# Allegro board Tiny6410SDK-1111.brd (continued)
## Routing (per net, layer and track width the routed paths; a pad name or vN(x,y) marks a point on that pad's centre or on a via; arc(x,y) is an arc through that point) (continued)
GND_AC97: length 43.5
  TOP w0.305: U7.40 89.13,32.02 ; 89.13,32.02 89.63,32.52 U7.34 ; 89.13,32.02 88.13,31.02 ; U7.26 90.13,28.52 U7.49 ; U7.18 87.63,30.52 U7.49 ; U7.49 88.13,31.02 ; 88.13,31.02 U7.42
  TOP w0.508: C49.1 v1(91.82,38.48) ; C48.1 v1(88.01,39.5) ; R30.2 89.53,20.7 v1(88.9,21.34) ; C38.1 v1(97.16,34.42) ; C57.1 v1(97.16,31.62) ; C51.1 C53.1 86.87,22.35 86.49,21.97 v1(86.49,21.46) ; C34.2 v1(92.46,21.59) ; C23.1 v1(97.16,35.81) ; C39.1 v1(97.16,27.43) ; C40.1 v1(97.16,30.23) ; C33.2 v1(93.85,21.72) ; C60.1 v1(97.16,33.02) ; R26.2 v1(77.57,23.22) ; C27.1 v1(92.58,17.02) ; v1(97.16,26.42) 96.77,26.04 C25.1 ; C26.1 v1(97.16,28.83) ; C52.1 v1(91.06,21.46)
  TOP w0.559: v1(77.72,22.1) 78.61,22.99 R26.2 ; C61.1 80.14,27.69 79.73,27.28 v1(79.73,27.01)
  vias: v1(79.38,19.68) v1(79.38,18.54) v1(83.57,21.46) v1(84.71,21.46) v1(85.98,28.96) v1(86.11,32.64) v1(86.11,30.99) v1(88.01,29.08) v1(88.14,32.64) v1(88.14,30.86) v1(89.53,30.86) v1(89.53,29.21)
GND_EARTH: length 4.2
  TOP w0.508: LAN.8 68.45,19.88 68.45,22.1 C145.1
VBUS: length 139.8
  TOP w0.203: C17.1 104.9,17.65
  TOP w0.508: MINIUSB.1 98.42,12.19 99.06,12.83 99.95,12.83 ; v1(31.02,101.01) 31.02,98.52 43.2,86.33 43.22,86.33 44.03,85.52 49.58,85.52 v1(49.78,85.72)
  TOP w0.762: v1(105.03,19.05) 104.9,18.92 104.9,17.65 104.65,17.4 C18.2 104.39,15.24 104.39,14.61 103.38,13.59 100.97,13.59 100.2,12.83 99.95,12.83
  BOTTOM w0.203: v1(31.02,101.01) 31.02,103.02 TINY6410.A27
  BOTTOM w0.508: v1(105.03,19.05) 105.03,21.84 103.89,22.99 103.89,37.8 101.42,40.26 101.42,41.23 94.06,48.59 85.27,48.59 50.09,83.77 50.09,85.17 49.78,85.47 v1(49.78,85.72)
VDD5V: length 601.3
  TOP w0.229: LCD2.1 169.57,72.92 170.07,73.42 LCD2.2
  TOP w0.305: LCD1.2 149.27,66.59 149.73,67.06 149.77,67.02 LCD1.1 ; R42.1 103.68,47.42 105.08,47.42 106.58,48.92 U6.10 109.73,48.92
  TOP w0.559: R43.1 102.84,44.98 103.76,44.07 109.47,44.07 111.63,46.23 111.63,48.77 v1(110.62,49.78) 109.75,48.92 109.73,48.92 ; C1.1 28.45,24.62 ; C1.1 28.45,21.45 ; C1.1 30.29,23.03 ; 169.57,72.92 169.48,72.83 ; 30.35,24.89 C3.1 32.13,23.6
  TOP w0.762: R78.1 174.07,37.9 U12.3 175.12,41.66 173.3,43.48 USBH2.1 ; v1(76.02,124.6) 76.15,124.47 76.15,119.08 76.93,118.29 CON1.3 ; C1.1 25.86,23.03 ; v1(66.93,124.6) 66.93,116.94 66.07,116.08 CON2.5
  TOP w1.27: 163.96,70.74 163.96,70.74 165.39,69.31 165.39,69.25 175.65,58.98 LCD3.2 LCD3.1 ; 163.96,70.74 166.05,72.83 169.48,72.83 ; 163.96,70.74 160.78,67.56 v2(156.59,67.56) 150.31,67.56 149.77,67.02 ; U5.3 30.4,21.08 C1.1
  TOP w1.524: TINY6410.A1 6,107.92 4.83,109.09 4.83,115.44 12.06,122.68 22.23,122.68 26.16,118.75 26.16,117.37 USBH3.1 ; USBH1.1 162.16,112.5 155.45,105.79 v2(155.32,105.79) 109.98,105.79 109.09,104.9 v2(108.71,104.9)
  TOP w2.032: 19.04,25 v2(20.04,24) 19.63,23.59 15.43,23.59 CON8.1 10.92,22.48 8.26,19.81 7.24,19.81 5.9,18.47 S1.2
  BOTTOM w0.762: 39.97,115.08 40.12,114.94 50.01,114.94 51.02,113.93 CON3.3 ; CON5.2 108.74,93.5 107.57,92.33 107.57,87.5 106.68,86.61 106.68,59.44 109.09,57.02 109.09,50.94 109.72,50.32 110.08,50.32 v1(110.62,49.78)
  BOTTOM w1.27: LCD3.1 177.99,53.91 167.56,43.48 USBH2.1 161.69,38.06 BUZZER.1
  BOTTOM w1.524: CON5.2 109,104.61 v2(108.71,104.9) 103.12,110.49 99.95,110.49 92.58,117.86 92.58,121.61 89.6,124.6 v1(76.02,124.6) v1(66.93,124.6) 45.14,124.6 40.68,120.13 40.68,118.05 39.86,117.23 39.86,115.19 ; 39.86,115.19 28.34,115.19 USBH3.1 ; 39.86,115.19 39.97,115.08 CON4.3 ; v2(20.04,24) 16.38,27.66 16.38,45.59 13.34,48.64 3.81,48.64 2.24,50.21 2.24,101.43 4.45,103.63 5.63,103.63 TINY6410.A1 ; v2(156.59,67.56) 156.59,92.2 159.13,94.74 159.13,100.84 155.32,104.65 v2(155.32,105.79)
  BOTTOM w2.032: v2(20.04,24) v1(21.84,24)
VDD33V: length 791.3
  TOP w0.254: U8.30 62.32,47.2 62.36,47.24 ; 82.48,29.52 U7.9 ; U7.1 83.82,33.86 83.82,34.64 82.64,35.81 C50.1 ; U8.42 58.8,41.28 59.31,40.77 59.31,39.24 59.41,39.14 v1(59.41,39.12)
  TOP w0.305: 67.92,42.7 67.34,43.28 U8.23
  TOP w0.406: 37.72,51.18 R1.1 37.72,52.35 R41.2
  TOP w0.508: v1(80.52,29.72) 80.72,29.52 82.48,29.52 ; R8.2 R5.2 122.79,27.18 C21.2 ; C8.1 62.36,48.26 62.36,47.24
  TOP w0.559: R3.2 v1(34.19,40.36) ; v1(34.19,40.36) 34.16,40.39 C15.2 ; v1(34.19,40.36) 33.81,40.36 33.65,40.51 CON6.4 ; R76.2 R72.2 74.04,96.52 v1(73.79,96.27) ; C43.2 93.37,110.21 v1(93.34,110.24) ; C43.2 97.05,109.07 99.69,106.43 U1.16 ; C43.2 92.79,108.48 92.79,108.41 91.85,107.47 C14.2 90.98,106.43 U2.16 ; R11.1 23.37,21.34 24.26,20.45 24.26,14.35 25.65,12.95 32.89,12.95 38.35,18.41 38.35,21.03 U5.4 ; R9.2 34.85,36.58 v1(35.23,36.96) ; v1(34.34,34.42) 34.19,34.26 R10.2 ; R74.2 v1(68.33,95.12) ; 119.72,40.64 120.08,40.28 ; 119.72,40.64 99.82,40.64 ; 119.72,40.64 119.76,40.64 120.08,40.32 120.08,40.28 ; 120.08,40.28 v1(121.24,39.12) 121.24,33.15 120.57,32.48 120.57,31.78 121.24,31.12 R8.2 ; 99.82,40.64 v2(98.81,39.62) ; 99.82,40.64 99.69,40.64 98.68,39.62 ; C62.1 171.83,32.77 163.45,32.77 157.99,38.23 v1(157.99,38.99) ; R20.2 v1(68.33,96.65) ; R71.2 v1(68.33,99.69) ; v1(63.45,49.02) 63.37,49.02 62.76,48.41 C8.1 ; R77.2 73.91,98.04 v1(73.79,98.17) ; 37.72,51.18 v1(37.92,50.98) ; v2(81.41,42.04) 82.11,41.34 82.11,36.17 C50.1 ; R6.2 v1(34.19,46.99) ; U4.8 C21.2 122.79,25.78 123.83,24.75 123.83,21.46 119.81,17.45 119.81,17.38 119.53,17.09 119.46,17.09 C20.2 116.59,16.51 116.46,16.64 116.2,16.64 115.44,15.88 115.44,10.71 115.52,10.63 115.52,7.4 114.45,6.33 114.41,6.33 112.65,4.57 112.06,4.57 111.64,4.15 111.62,4.15 R33.2 111.48,3.05 117.88,3.05 R35.2 R37.2 R40.2 134.85,3.53 135.51,4.19 143.76,4.19 144.42,3.53 R38.2 R36.2 R47.2 R48.2 ; 25.27,114.82 24.78,114.82 24.38,114.43 R61.2 ; R18.2 v1(68.33,90.55) ; R73.2 v1(68.33,92.08) ; R39.2 v1(55.5,27.05) ; R4.2 34.19,50.27 v1(33.27,51.18) ; R19.2 v1(68.33,93.6) ; R7.2 v1(34.19,44.75) ; R75.2 v1(68.33,98.17)
  TOP w0.762: 48.28,23.37 48.28,25.38 42.8,30.86 v1(35.71,30.86) R12.2 ; U9.6 27.81,109.98 28.37,110.54 28.37,112.73 C45.1 ; 67.92,42.7 68.71,41.91 C54.1 69.72,41.91 v1(70.36,41.27) 70.36,40.77 69.34,39.75 69.34,23.37 71.63,21.08 74.68,21.08 ; R24.2 52.73,26.42 v2(51.18,26.42) ; v2(43.05,109.35) 35.05,109.35 33.81,110.59 33.81,111.3 32.33,112.78 C45.1 ; C45.1 28,113.09 28,113.47 26.66,114.82 25.27,114.82 ; v2(78.23,79.55) v2(101.85,79.55) ; v2(105.41,89.15) 105.41,91.82 109.73,96.14 112.52,96.14 114.3,97.92 v1(127,97.92) 133.69,97.92 136.35,95.25 138.75,95.25 CON11.1
  TOP w1.016: v2(97.66,58.55) 94.48,58.55 Y5.4 87.16,48.3 86.07,47.22 R45.2 85.72,46.74 81.41,42.42 v2(81.41,42.04)
  TOP w1.27: v2(51.18,26.42) 51.18,25.91 48.64,23.37 C2.1 48.28,23.37 C73.1 U5.4 U5.2
  BOTTOM w0.559: 55.5,27.18 55.44,27.24 ; v1(80.52,29.72) 80.52,33.15 79.5,34.16 79.5,39.5 80.64,40.64 80.64,41.27 ; v1(73.79,96.27) v1(73.79,98.17) v1(68.33,98.17) ; CON5.20 v1(127,97.92) ; v1(157.99,38.99) 157.86,38.86 121.5,38.86 v1(121.24,39.12)
  BOTTOM w0.762: v1(35.71,30.86) 34.04,32.54 34.04,33.6 34.34,33.91 v1(34.34,34.42) 35.23,35.31 v1(35.23,36.96) 34.32,36.96 32.89,38.38 32.89,39.07 v1(34.19,40.36) v1(34.19,44.75) v1(34.19,46.99) 34.19,49.56 33.27,50.47 v1(33.27,51.18) 36.55,51.18 36.75,50.98 v1(37.92,50.98) ; v2(78.23,79.55) 77.75,79.55 68.33,88.98 v1(68.33,90.55) v1(68.33,92.08) v1(68.33,93.6) v1(68.33,95.12) v1(68.33,96.65) v1(68.33,98.17) v1(68.33,99.69) 68.58,99.95 68.58,104.78 65.79,107.57 44.83,107.57 v2(43.05,109.35) ; CON11.1 139,95.78 137.78,96.99 137.78,103.74 155.7,121.67 160.02,121.67 163.13,124.77 163.13,127.42 163.71,128 166.57,128 167.39,127.18 U10.3 ; v2(101.85,79.55) 101.85,79.76 101.98,79.88 101.98,85.14 105.41,88.57 v2(105.41,89.15) 105.41,105.79 102.23,108.97 99.31,108.97 98.04,110.24 v1(93.34,110.24) ; v2(81.41,42.04) 83.44,44.07 94.36,44.07 v2(98.81,39.62) 99.19,39.24 99.19,21.34 97.92,20.07 97.92,17.27 100.19,15 W1.2
  BOTTOM w0.889: 67.31,41.27 67.92,41.88 67.92,44.6 63.5,49.02 v1(63.45,49.02)
  BOTTOM w1.016: v2(97.66,58.55) 97.79,58.55 101.85,62.61 v2(101.85,79.55)
  BOTTOM w1.27: v1(55.5,27.05) 55.5,27.3 55.75,27.56 55.75,35.69 59.05,38.99 59.28,38.99 v1(59.41,39.12) 65.15,39.12 67.31,41.27 v1(70.36,41.27) 80.64,41.27 v2(81.41,42.04) ; 55.44,27.24 54.61,26.42 v2(51.18,26.42)
VDD_AC97: length 9.6
  TOP w0.203: U7.25 91.99,28.02 92.2,27.81 92.2,27.56 v1(91.82,27.18)
  TOP w0.254: v1(90.42,35.81) 90.42,35.69 90.13,35.39 U7.38 ; U7.43 v1(87.63,35.68)
  TOP w0.508: v1(90.42,35.81) 90.68,36.07 C49.2 ; v1(87.63,35.68) 88.01,36.06 C48.2
  BOTTOM w0.762: v1(90.42,35.81) 90.29,35.68 v1(87.63,35.68)
  vias: v1(82.04,25.91) v1(83.57,25.53) v1(84.71,25.53)
VDDBAT: length 9.2
  TOP w0.508: BAT1.1 111.63,19.56 113.03,18.16 113.03,16.71 D1.2 111.3,16.64 R13.2
VDDIN: length 15.2
  TOP w2.032: CN1.1 15.24,11.18 15.24,13.94 CON8.4 14.2,14.73 8.76,14.73 8.02,15.47 S1.3
VDDRTC: length 150.2
  TOP w0.254: TINY6410.B4 7.06,58.94 7.06,61.21
  TOP w0.381: v1(103.38,19.68) 103.76,20.07 107.95,20.07 109.35,18.67 109.35,16.51 110.24,15.62 R13.1 ; 7.06,61.21 7.06,62.56 15.37,70.87 24.13,70.87 25.02,71.75 59.18,71.75 v1(59.44,71.5)
  BOTTOM w0.381: v1(103.38,19.68) 103.25,19.81 103.25,21.84 100.37,24.73 100.37,39.97 99.57,40.77 98.93,40.77 94.36,45.34 80.77,45.34 74.17,51.94 74.17,56.13 59.44,70.87 v1(59.44,71.5)
AC97_BITCLK: length 76.3
  TOP w0.203: TINY6410.B29 34,61.05 36.78,63.83 64.37,63.83 70.06,58.14 71.53,58.14 79.25,50.42 79.25,32.78 80.18,31.85 81.68,31.85 82.51,31.02 U7.6
AC97_RSTN: length 77.8
  TOP w0.203: TINY6410.B30 34.91,57.09 38.72,57.09 38.91,57.28 38.91,58.35 39.48,58.91 40.37,58.91 41.09,59.63 41.09,60.38 42.91,62.2 63.7,62.2 76.89,49.02 76.89,44.62 77.83,43.68 77.83,32.05 79.22,30.66 79.22,29.31 80.02,28.52 U7.11
AC97_SDI: length 70.9
  TOP w0.203: U7.8 82.77,30.02 82.68,30.11 82.21,30.11 82.13,30.2 81.05,30.2 78.68,32.58 78.68,43.98 77.7,44.96 77.7,49.36 64.04,63.02 40.03,63.02 38,60.99 TINY6410.B33
AC97_SDO: length 81.7
  TOP w0.203: U7.5 83.24,31.52 83.19,31.47 82.64,31.47 81.84,32.26 80.35,32.26 79.65,32.95 79.65,50.9 72.01,58.55 70.23,58.55 64.54,64.24 36.04,64.24 33.09,61.28 33.09,59.62 33.62,59.09 34.91,59.09 TINY6410.B32
AC97_SYNC: length 74.6
  TOP w0.203: U7.10 83.31,29.02 83.25,28.96 80.16,28.96 79.66,29.45 79.66,30.85 78.23,32.28 78.23,43.85 77.29,44.79 77.29,49.19 63.87,62.61 41.15,62.61 39.09,60.55 39.09,59.79 38.35,59.05 37.47,59.05 36.52,60 TINY6410.B31
AIN0: length 120.6
  TOP w0.203: W1.3 99.99,19.47 101.35,20.83 106.68,20.83 v1(107.19,21.34)
  BOTTOM w0.203: v1(107.19,21.34) 107,21.53 107,37.55 106.38,38.18 106.38,38.2 105.51,39.07 105.49,39.07 102.79,41.76 102.79,41.8 94.63,49.96 94.59,49.96 93.12,51.44 90.55,51.44 52.86,89.13 52.86,94.97 46.91,100.91 46.91,102.38 46.38,102.91 45.09,102.91 TINY6410.A39
CTSN1: length 200.2
  TOP w0.203: U2.9 88.27,97.54 86.74,96.01 81.84,96.01 v1(81.54,95.72) ; CON5.9 117,91.37 115.57,89.94 114.76,89.94 113.92,89.1 113.56,89.1 111.5,87.05 107.79,87.05 107.49,86.74 82.27,86.74 v1(82.01,87) ; v1(87.88,66.8) 87.12,66.8 86.51,66.19 71.79,66.19 67.24,70.74 24.7,70.74 24.34,70.37 17.08,70.37 14.88,68.17 14.88,68.03 9.09,62.24 9.09,58.91 TINY6410.B6
  BOTTOM w0.203: CON2.2 60.07,111.25 61.34,109.98 67.76,109.98 68.55,109.19 75.2,109.19 77.22,107.17 77.22,99.82 80.01,97.03 80.64,97.03 81.54,96.13 v1(81.54,95.72) 81.78,95.48 81.78,87.23 v1(82.01,87) 82.01,86.41 85.57,82.85 85.57,81.81 87.88,79.5 v1(87.88,66.8)
DACOUT0: length 27.8
  TOP w0.203: R59.1 29.97,107.06 31.5,105.54 54.46,105.54 TINY6410.A51
DM9000_RX+: length 22.7
  TOP w0.203: LAN.3 62.55,17.34 64.52,19.3 64.52,20.7 63.98,21.23 63.98,27.33 60.83,30.48 60.83,32.66 R67.2 60.32,33.67 U8.3
DM9000_RX-: length 19.9
  TOP w0.203: LAN.6 64.39,21.4 64.39,27.5 61.24,30.65 61.24,32.56 R68.2 61.98,33.43 60.82,34.59 U8.4
DM9000_TX+: length 27.1
  TOP w0.203: U8.7 62.32,35.47 62.61,35.18 64.26,35.18 v1(64.9,34.54) 65.53,33.91 65.53,33.58 65.38,33.43 R62.2
  BOTTOM w0.203: LAN.1 59.94,17.72 59.94,18.47 58.62,19.79 58.62,21.53 65.41,28.32 65.41,34.04 v1(64.9,34.54)
DM9000_TX-: length 26.3
  TOP w0.203: U8.8 62.82,35.74 62.99,35.56 65.15,35.56 66.04,34.67 v1(66.04,34.57) 65.91,34.44 65.91,33.58 66.07,33.43 R66.2
  BOTTOM w0.203: LAN.2 60.38,19.42 59.56,19.42 59.02,19.96 59.02,21.37 65.81,28.15 65.81,34.34 v1(66.04,34.57)
EINT0: length 132.1
  TOP w0.203: K1.2 K1.1 111,8.81 R33.1
  BOTTOM w0.203: K1.2 113.87,15.79 107.7,21.96 107.7,37.46 103.2,41.96 103.2,41.96 94.8,50.37 94.79,50.37 89.23,55.93 86.69,55.93 57.08,85.53 57.08,103.08 TINY6410.A53
EINT1: length 132.5
  TOP w0.203: R35.1 118.36,11.05 K2.1 117.12,12.35 117.73,12.95 121.18,12.95 v1(121.41,13.18) 122.58,13.18 K2.2
  BOTTOM w0.203: TINY6410.A54 57.56,101.56 57.56,85.71 86.93,56.34 89.4,56.34 94.96,50.77 94.96,50.77 103.61,42.13 103.61,42.13 107.41,38.32 108.11,38.32 111.44,34.99 112.01,34.99 112.53,34.46 112.53,34.02 115.7,30.86 115.7,26.8 121.41,21.08 v1(121.41,13.18)
EINT2: length 156.4
  TOP w0.203: K3.2 K3.1 147.32,10.79 R36.1
  BOTTOM w0.203: K3.1 143.51,14.61 134.49,14.61 132.84,16.26 125.35,16.26 123.32,18.29 123.32,28.28 117.07,34.52 113.05,34.52 112.18,35.39 111.61,35.39 108.28,38.73 107.58,38.73 104.01,42.3 104.01,42.3 95.13,51.18 95.13,51.18 89.57,56.74 87.1,56.74 59.08,84.76 59.08,103.08 TINY6410.A55
EINT3: length 138.8
  TOP w0.203: K4.2 K4.1 ; K4.1 v1(126.7,22.14) ; K4.1 128.52,10.5 R37.1
  BOTTOM w0.203: v1(126.7,22.14) 126.49,22.35 126.49,28.59 124.95,30.12 124.07,30.12 123.44,30.75 123.44,31.63 120.74,34.34 119.28,34.34 117.68,35.94 111.64,35.94 108.45,39.13 107.75,39.13 104.42,42.47 104.42,42.47 95.3,51.59 95.3,51.59 89.74,57.15 87.27,57.15 59.51,84.9 59.51,101.51 TINY6410.A56
EINT4: length 147.2
  TOP w0.203: R38.1 144.86,5.11 K5.2 K5.1 136.32,10.11 137.74,11.53 137.74,14.22 v1(136.5,15.47)
  BOTTOM w0.203: v1(136.5,15.47) 136.44,15.47 134.62,17.29 134.62,20.95 127.57,28 127.57,28.52 125.56,30.53 124.24,30.53 123.85,30.92 123.85,32.24 121.34,34.75 119.45,34.75 117.62,36.58 111.58,36.58 108.62,39.54 107.92,39.54 104.83,42.63 104.83,42.64 95.47,51.99 95.47,51.99 89.9,57.56 87.44,57.56 60.96,84.03 60.96,102.96 TINY6410.A57
EINT5: length 142.6
  TOP w0.203: R40.1 133.22,5.46 134.44,6.68 134.44,9.09 134.11,9.42 134.11,10.79 134.72,11.4 134.72,15.68 K6.1 K6.2
  BOTTOM w0.203: TINY6410.A58 61.42,101.42 61.42,84.15 87.6,57.96 89.87,57.96 90.07,57.96 95.63,52.4 95.64,52.4 105.23,42.81 105.23,42.8 108.09,39.95 108.78,39.95 111.75,36.98 118.04,36.98 119.87,35.15 121.56,35.15 128.14,28.57 128.14,28.07 135.23,20.98 135.23,18.38 K6.1
EINT7: length 22.6
  TOP w0.203: U8.34 60.32,46.39 58.67,48.03 58.67,48.59 51.77,55.5 v1(50.67,55.5)
  BOTTOM w0.203: v1(50.67,55.5) 50.16,56.01 47.21,56.01 46.27,56.95 45.05,56.95 TINY6410.B40
EINT8: length 234.3
  TOP w0.203: TINY6410.A30 33.45,101.45 33.45,99.26 44.83,87.88 44.83,87.25 v1(44.96,87.12) ; v1(44.07,97.79) 44.07,97.47 46,95.53 48.24,95.53 51.44,92.33 52.64,92.33 54.67,90.3 65.27,90.3 67.17,88.39 74.69,88.39 77.56,85.52 109.45,85.52 109.75,85.83 112.01,85.83 113.63,87.45 118.06,87.45 119.51,88.9 122.43,88.9 123.95,90.42 123.95,91.28 124.06,91.39 124.06,92.44 125,93.38 CON5.18 125.3,93.5 126.24,92.56 131.75,92.56 132.46,91.85 146.84,91.85 149.35,94.36 157.19,94.36 157.57,94.74 160.4,94.74 v1(161.04,95.38) ; R1.2 38.63,54.79 41.96,54.79 v1(42.55,55.37)
  BOTTOM w0.203: v1(42.55,55.37) 43,55.83 43,62.23 44.96,64.19 44.96,71.74 44.93,71.76 44.93,72.31 44.96,72.33 v1(44.96,87.12) ; v1(161.04,95.38) 160.78,95.63 160.78,100.71 158.37,103.12 158.37,112.65 166.12,120.4 U10.2 ; TINY6410.A30 34.68,101.32 34.68,101.32 37.8,98.2 38.63,98.2 39.14,97.69 43.1,97.69 43.2,97.79 v1(44.07,97.79)
EINT12: length 160.3
  TOP w0.203: TINY6410.B34 37.38,58 36.29,59.09 35.62,59.09 35.09,59.62 35.09,60.74 37.77,63.42 64.21,63.42 76.19,51.44 v1(77.09,51.44) ; U12.1 173.99,33.87 173.99,35.81 173.48,36.32 R78.2 170.31,36.32 166.5,40.13 v1(159.64,40.13) ; v1(98.93,41.83) 99.23,41.53 v1(113.41,41.53)
  BOTTOM w0.203: v1(159.64,40.13) 158.2,40.13 157.56,39.5 121.8,39.5 121.22,40.07 120.46,40.07 119.63,40.89 114.17,40.89 113.54,41.53 v1(113.41,41.53) ; v1(98.93,41.83) 98.81,41.95 98.81,42.04 94.54,46.3 84,46.3 78.87,51.44 v1(77.09,51.44)
EINT19: length 165.4
  TOP w0.203: R47.1 156.46,6.22 156.84,6.6 156.84,10.77 K7.1 ; K7.1 155.32,15.95 157.99,18.61 v1(157.99,20.32) ; K7.1 K7.2
  BOTTOM w0.203: TINY6410.A59 64.91,103.09 64.91,101.62 63.98,100.69 63.98,82.73 79.33,67.39 79.33,67.41 87.97,58.78 90.66,58.78 100.82,48.62 102.69,48.62 113.51,37.8 118.52,37.8 118.88,37.44 120.7,37.44 127.15,30.99 133.8,30.99 135.45,29.34 148.97,29.34 v1(157.99,20.32)
EINT20: length 164.2
  TOP w0.203: K8.2 K8.1 166.5,10.63 R48.1
  BOTTOM w0.203: K8.1 161.38,15.75 147.57,15.75 138.18,25.15 132.38,25.15 120.5,37.03 118.71,37.03 118.59,37.15 118.35,37.39 112.79,37.39 112.2,37.97 111.33,37.97 108.95,40.35 108.26,40.35 105.64,42.97 105.64,42.97 95.81,52.81 95.8,52.81 90.24,58.37 87.77,58.37 63.58,82.57 63.58,101.58 TINY6410.A60
GPE0: length 190.1
  TOP w0.203: v1(66.93,74.04) 68.33,74.04 73.48,68.88 116.11,68.88 119.89,72.67 130.56,72.67 130.64,72.75 131.19,72.75 132.3,71.63 132.51,71.63 133.63,70.51 133.63,70.21 135.25,68.58 v1(135.26,68.58) LCD1.30 ; v1(130.94,79.25) 130.94,79.5 133.73,82.3 149.77,82.3 155.54,88.06 167.49,88.06 168.03,87.52 170.72,87.52 170.81,87.43 LCD2.30 175.54,87.43 LCD3.30 ; v1(54.48,85.09) 54.13,85.45 52.17,85.45 51.69,84.96 43.8,84.96 42.99,85.78 42.97,85.78 30.23,98.52 30.23,101.77 TINY6410.A26
  BOTTOM w0.203: v1(54.48,85.09) 54.48,84.63 65.07,74.04 v1(66.93,74.04) ; v1(135.26,68.58) 133.42,70.43 133.42,70.72 131.75,72.39 131.75,78.44 v1(130.94,79.25)
HPL: length 48.9
  TOP w0.381: C41.2 85.93,42.8 85.34,42.8 84.07,41.53 v1(84.07,40.64) ; v1(80.44,17.45) 80.26,17.63 80.26,18.39 R31.1 80.42,18.54 C29.1 81.92,18.03 81.34,17.46 81.34,16.99 CON9.3 79.01,14.67 78.42,14.67 75.18,11.43 75.18,6.99 CON9.4
  BOTTOM w0.381: v1(84.07,40.64) 84.07,30.61 80.52,27.05 80.52,17.53 v1(80.44,17.45)
HPR: length 45
  TOP w0.381: v1(85.27,39.75) 85.27,40.37 85.69,40.8 85.96,40.8 C42.2 ; v1(82.53,17.42) 82.82,17.42 83.31,17.91 83.31,18.39 R32.1 83.57,18.64 84.73,18.64 C28.1 84.94,18.44 84.94,17.88 81.79,14.73 81.79,11.63 CON9.2 78.35,9.53 78.15,9.53 CON9.1
  BOTTOM w0.381: v1(82.53,17.42) 81.15,18.8 81.15,26.8 84.84,30.48 84.84,39.34 85.24,39.75 v1(85.27,39.75)
HSYNC: length 193.8
  TOP w0.203: 176.4,92.02 176.39,92.04 175.99,92.04 ; 176.4,92.02 177.04,92.02 LCD3.35 ; 176.4,92.02 175.71,92.02 173.61,89.93 LCD2.35 168.5,89.93 167.49,90.93 160.66,90.93 160.18,90.46 150.16,90.46 147.16,87.45 130.9,87.45 126.66,83.21 126.09,83.21 125.91,83.03 124.72,83.03 124.33,82.65 124.33,82.6 v1(124.05,82.32) 123.8,82.07 115.47,82.07 111.74,78.33 76.74,78.33 71.59,83.48 41.49,83.48 27.56,97.41 27.56,101.56 TINY6410.A24 ; LCD1.35 132.76,66.77 130.85,68.68 128.42,68.68 v1(126.62,70.48)
  BOTTOM w0.203: v1(124.05,82.32) 124.05,82.22 123.24,81.41 123.24,72.85 125.6,70.48 v1(126.62,70.48)
I2CSCL: length 247.7
  TOP w0.203: TINY6410.B19 24,60.58 28.47,65.05 64.88,65.05 70.57,59.36 72.72,59.36 73.79,58.29 92.14,58.29 93.92,60.07 123,60.07 132.24,50.83 142.71,50.83 v1(143.13,50.42) 142.88,50.16 142.88,48.39 133.86,39.37 128.21,39.37 125.39,36.56 125.39,33.23 127.25,31.37 127.25,29.21 126.9,28.86 U4.6 124.87,28.86 124.74,28.73 R5.1 ; CON11.5 143,95.31 141.85,94.15 135.9,94.15 133.54,96.52 122.68,96.52 120.78,94.61 114.55,94.61 114.05,94.11 114.05,92.55 CON5.5
  BOTTOM w0.203: v1(143.13,50.42) 142.88,50.67 142.88,64.26 141.07,66.07 141.07,76.94 142.49,78.36 142.49,94.99 CON11.5
I2CSDA: length 247.2
  TOP w0.203: CON5.6 113,93.7 114.43,95.12 120.52,95.12 122.56,97.16 133.48,97.16 136.07,94.56 141.39,94.56 141.94,95.11 141.94,96.44 CON11.6 ; TINY6410.B20 25.09,59.09 25.09,60.65 29.08,64.64 64.71,64.64 70.4,58.95 72.18,58.95 73.24,57.89 92.31,57.89 93.99,59.56 122.94,59.56 132.4,50.1 141.54,50.1 v1(141.73,49.91) 141.86,49.78 141.86,48.39 133.48,40.01 128.27,40.01 125.43,37.16 124.33,37.16 123.44,36.27 123.44,31.14 R8.1 123.2,30.13 U4.5
  BOTTOM w0.203: v1(141.73,49.91) 141.86,50.04 141.86,64.14 140.48,65.51 140.48,76.93 141.99,78.44 141.99,95.08 142.06,95.16 142.06,96.56 CON11.6
LADDR2: length 26
  TOP w0.203: TINY6410.B37 43.8,61.8 47.68,61.8 49.02,60.45 49.02,57.53 50.04,56.52 52.7,56.52 59.11,50.11 60.27,50.11 R14.1
LANLED: length 50.5
  TOP w0.203: U8.39 59.2,42.78 60.07,41.91 60.07,38.73 59.28,37.95 59.13,37.95 58.67,37.49 58.67,36.32 58.29,35.94 54.99,35.94 54.33,35.28 54.33,31.24 54.64,30.94 54.64,18.77 59.05,14.35 61.72,14.35 68.58,7.49 68.58,6.58 LAN.11
LDATA0: length 30.7
  TOP w0.203: U8.18 65.46,40.78 65.15,41.1 65.15,41.36 v1(64.49,42.01)
  BOTTOM w0.203: v1(64.49,42.01) 63.25,40.77 60.27,40.77 55.12,45.92 55.12,53.47 51.05,57.53 51.05,58.95 TINY6410.B45
LDATA1: length 28.6
  TOP w0.203: v1(64.54,40.84) 64.59,40.84 65.15,40.28 U8.17
  BOTTOM w0.203: v1(64.54,40.84) 63.96,40.26 60.06,40.26 54.61,45.71 54.61,53.21 50,57.82 TINY6410.B46
LDATA2: length 29.5
  TOP w0.203: v1(63.6,42.2) 63.61,42.18 63.61,40.83 64.66,39.78 U8.16
  BOTTOM w0.203: TINY6410.B47 52.96,59.04 52.96,57.28 56.16,54.07 56.16,46.07 60.45,41.78 62.33,41.78 62.71,42.16 63.57,42.16 v1(63.6,42.2)
LDATA3: length 27.6
  TOP w0.203: U8.14 65.09,38.78 62.95,40.92 v1(62.95,41.47)
  BOTTOM w0.203: v1(62.95,41.47) 62.75,41.27 60.38,41.27 55.75,45.9 55.75,53.72 52,57.47 TINY6410.B48
LDATA4: length 29
  TOP w0.203: U8.13 64.97,38.28 62.2,41.05 62.2,41.94 62.43,42.17 62.43,43.1 v1(62.48,43.15)
  BOTTOM w0.203: TINY6410.B49 55.09,58.91 55.09,57.18 57.28,54.99 57.28,46.28 60.4,43.15 v1(62.48,43.15)
LDATA5: length 26.4
  TOP w0.203: v1(61.77,42.44) 61.77,40.9 64.82,37.86 U8.12
  BOTTOM w0.203: TINY6410.B50 54,57.51 56.77,54.74 56.77,46.15 60.5,42.42 61.57,42.42 61.59,42.44 v1(61.77,42.44)
LDATA6: length 27.3
  TOP w0.203: v1(61.67,43.87) 61.67,43.51 61.11,42.95 61.11,40.99 64.32,37.78 U8.11
  BOTTOM w0.203: v1(61.67,43.87) 61.01,44.53 60.58,44.53 58.48,46.62 58.48,56.2 57.02,57.66 57.02,58.98 TINY6410.B51
LDATA7: length 24.4
  TOP w0.203: U8.10 63.82,37.71 60.71,40.82 v1(60.71,43.86)
  BOTTOM w0.203: TINY6410.B52 57.91,56.09 57.91,46.58 60.55,43.94 60.62,43.94 v1(60.71,43.86)
LDATA8: length 17.4
  TOP w0.203: TINY6410.B53 56.91,58.91 56.91,55.99 59.05,53.85 59.05,53.09 59.23,52.91 59.23,52.89 59.62,52.5 59.89,52.5 60.83,51.56 60.83,50.93 61.47,50.29 61.47,47.12 61.82,46.77 U8.31
LDATA9: length 15.8
  TOP w0.203: U8.29 62.82,46.69 64.11,47.98 64.11,51.16 58.46,56.81 58.46,56.82 58,57.28 TINY6410.B54
LDATA10: length 17.9
  TOP w0.203: U8.28 63.32,46.55 64.52,47.75 64.52,51.82 59.05,57.28 59.05,59.05 TINY6410.B55
LDATA11: length 15.4
  TOP w0.203: TINY6410.B56 60,57.22 65.02,52.2 65.02,47.5 63.82,46.29 U8.27
LDATA12: length 17.4
  TOP w0.203: TINY6410.B57 61.09,59.09 61.09,56.85 65.46,52.48 65.46,47.29 64.32,46.16 U8.26
LDATA13: length 14.9
  TOP w0.203: U8.25 64.82,46.02 65.96,47.17 65.96,52.6 62,56.57 TINY6410.B58
LDATA14: length 18.5
  TOP w0.203: TINY6410.B59 67.31,56.69 67.31,44.07 67.02,43.78 U8.24
LDATA15: length 18
  TOP w0.203: U8.22 65.17,42.78 65.02,42.93 65.02,43.94 65.39,44.31 65.39,45.91 66.47,46.99 66.47,52.96 64,55.43 64,58 TINY6410.B60
LINKLED: length 67.2
  TOP w0.203: U8.38 56.67,43.28 51.82,48.13 46.74,48.13 45.86,47.25 45.86,36.31 47.55,34.62 53.14,34.62 53.85,33.91 53.85,30.99 54.23,30.61 54.23,18.1 53.34,17.21 53.34,12.45 54.23,11.56 54.23,8.64 55.24,7.62 58.17,7.62 59.7,6.09 LAN.10
LNOE: length 18.5
  TOP w0.203: TINY6410.B44 48,57.24 50.4,54.84 51.82,54.84 57.91,48.74 57.91,48.13 59.82,46.23 U8.35
LNWE: length 21.6
  TOP w0.203: TINY6410.B43 47.09,59.09 47.09,56.55 49.2,54.43 51.61,54.43 57.28,48.77 57.28,48.13 59.32,46.09 U8.36
M_NRESET: length 51.3
  TOP w0.203: v1(36.58,55.24) 36.58,51.87 37,51.45 37,50.66 38.94,48.72 40.01,48.72 41.78,46.94 RST.1 RST.2
  BOTTOM w0.203: TINY6410.B3 8.89,59.11 8.89,58.4 8.91,58.38 8.91,57.63 11.53,55.02 31.4,55.02 32.31,54.1 35.31,54.1 36.45,55.24 v1(36.58,55.24)
MIC: length 7.8
  TOP w0.203: C37.2 89.66,21.84 90.3,21.21 90.3,19.28 R25.2 R30.1 R29.1
MICBIAS: length 16.9
  TOP w0.203: R29.2 88.01,20.95 v1(87.76,21.21) ; v1(93.09,28.57) 93.22,28.7 94.36,28.7 C26.2 C40.2 93.98,30.23 93.27,29.52 U7.28
  BOTTOM w0.203: v1(93.09,28.57) 93.09,26.92 87.76,21.59 v1(87.76,21.21)
NCS1: length 25.2
  TOP w0.203: TINY6410.B39 44.91,59.09 44.91,55.67 46.61,53.98 51.18,53.98 56.13,49.02 56.13,44.58 56.93,43.78 U8.37
NET_AVDD25: length 40
  TOP w0.203: U8.9 63.32,37.63 62.98,37.97 60.07,37.97 59.82,37.72 U8.2 59.82,34.8 59.31,34.29 59.31,32.38 58.83,31.9 C36.2
  TOP w0.508: C36.2 C35.2 57.02,29.21 C74.1 56.77,26.67 56.77,18.11 58.68,16.19 58.74,16.19 59.18,15.75 63.05,15.75 LAN.5
  BOTTOM w0.508: LAN.5 64.64,18.61 LAN.4
NETBUZZER/2: length 6.3
  TOP w0.381: BUZZER.2 153.16,26.8 Q1.C
NETC4/1: length 3
  TOP w0.406: C4.1 81.18,105.66 81.79,105.66 82.55,106.43 U2.1
NETC4/2: length 11.4
  TOP w0.406: C4.2 80.42,106.43 81.66,106.43 82.8,107.57 84.84,107.57 85.34,107.06 85.34,104.39 84.84,103.89 U2.3
NETC5/1: length 3.2
  TOP w0.406: U2.2 83.57,105.03 82.68,105.03 81.41,103.76 C5.1
NETC6/1: length 2.7
  TOP w0.508: C6.1 81.13,100.08 U2.6
NETC33/1: length 5.1
  TOP w0.203: U7.24 90.63,26.72 91.19,26.16 92.84,26.16 93.85,25.15 C33.1
NETC34/1: length 3.7
  TOP w0.203: C34.1 90.13,26.58 U7.23
NETC37/1: length 3
  TOP w0.203: C37.1 89.13,24.79 U7.21
NETC44/2: length 3
  TOP w0.508: C44.2 29.81,108.97 29,108.15 27.94,108.15 27.89,108.1 U9.4
NETC51/2: length 2.9
  TOP w0.203: U7.20 88.63,25.39 88.27,25.02 C51.2
NETC52/2: length 3.4
  TOP w0.203: U7.22 89.63,25.68 C52.2
NETC53/2: length 3.3
  TOP w0.203: U7.19 88.13,26.54 86.87,25.27 C53.2
NETC55/1: length 2.8
  TOP w0.406: C55.1 93.95,105.51 94.87,106.43 U1.1
NETC55/2: length 10.8
  TOP w0.406: C55.2 91.85,105.69 92.58,106.43 94.01,106.43 94.72,107.14 94.82,107.14 95.11,107.42 96.54,107.42 97.28,106.68 97.28,104.14 97.03,103.89 U1.3
NETC56/1: length 3
  TOP w0.406: C56.1 94.79,105.16 U1.2
NETC57/2: length 3.5
  TOP w0.203: U7.29 92.63,30.02 94.23,31.62 C57.2
NETC59/1: length 2.4
  TOP w0.406: C59.1 93.47,100.08 U1.6
NETC60/2: length 4.1
  TOP w0.203: C60.2 94.23,33.02 93.6,32.38 93.6,31.99 92.13,30.52 U7.30
NETC61/2: length 2.1
  TOP w0.203: C61.2 83.31,27.69 83.65,28.02 U7.12
NETLAN/9: length 21.4
  TOP w0.203: R24.1 53.72,23.85 53.72,18.29 52.83,17.4 52.83,12.32 53.72,11.43 53.72,8.38 54.99,7.11 56.35,7.11 LAN.9
NETLAN/12: length 26.3
  TOP w0.203: R39.1 55.12,23.85 55.12,18.92 59.18,14.86 61.86,14.86 LAN.12
NETLED_3.3/1: length 2.4
  TOP w0.203: R11.2 19.79,19.37 LED_3V3.1
NETR14/2: length 3.3
  TOP w0.203: R14.2 60.58,47.35 61.32,46.61 U8.32
NETR23/2: length 1.9
  TOP w0.381: R23.2 147.96,22.63 Q1.B
NETR25/1: length 24.2
  TOP w0.305: C27.2 93.47,19.18 93.47,16.64 92.5,15.66 88.52,15.66 CON10.3 87.52,13.66 86.52,12.66 86.52,11.66 CON10.1 85.78,10.4 85.98,10.4 CON10.2 85.52,6.86 CON10.4
  TOP w0.381: R25.1 92.56,20.09 C27.2
NETR27/1: length 18.6
  TOP w0.254: U7.2 83.61,33.02 83.31,33.32 83.31,34 82.39,34.92 80.39,34.92 80.09,35.23 80.09,44.25 R27.1
NETR28/1: length 2
  TOP w0.203: R28.1 82.83,33.15 83.46,32.52 U7.3
NETR42/2: length 4.5
  TOP w0.203: R42.2 105.73,49.57 U6.9
NETR43/2: length 4.4
  TOP w0.203: U6.14 106.14,46.32 104.9,45.09 R43.2
NETR45/1: length 8.6
  TOP w0.254: R45.1 85.45,48.79 84.45,49.78 84.45,53.09 86.79,55.42 Y5.1
NETR46/1: length 5.7
  TOP w0.508: R46.1 16.32,112.9 C46.2 C47.2
NETR46/2: length 16.2
  TOP w0.508: R46.2 14.71,115.34 12.55,117.5 CON7.2 11.71,117.5 10.79,116.59 10.79,109.7 CON7.1
NETR54/2: length 46.7
  TOP w0.203: U6.12 107.56,47.62 106.68,46.74 104.52,46.74 C30.1 104.22,46.61 103.44,45.83 102.25,45.83 102.07,45.66 102.07,44.23 102.87,43.43 109.67,43.43 112.39,46.16 112.39,53.72 116.84,58.17 122.35,58.17 123.22,57.29 123.22,54.26 122.17,53.21 R54.2
NETR59/2: length 3
  TOP w0.203: R59.2 31.55,108.92 C44.1 31.42,109.04 R60.2
NETR62/1: length 3.2
  TOP w0.203: R62.1 R66.1 C148.2
NETR67/1: length 6.9
  TOP w0.203: R68.1 C149.2 63.63,31.37 63.12,30.86 v1(62.23,30.86) ; R67.1 v1(60.07,30.73)
  BOTTOM w0.203: v1(62.23,30.86) 62.1,30.73 v1(60.07,30.73)
NETU1/4: length 4.4
  TOP w0.406: U1.4 94.2,102.62 94,102.82 92.71,102.82 C58.1
NETU1/5: length 2.6
  TOP w0.406: U1.5 93.98,101.35 C58.2
NETU2/4: length 4.6
  TOP w0.406: C7.1 80.37,102.82 81.65,102.82 81.85,102.62 U2.4
NETU2/5: length 2.9
  TOP w0.508: C7.2 81.64,101.35 U2.5
NETU7/27: length 5.3
  TOP w0.203: U7.27 92.26,29.02 92.43,28.85 92.43,28.19 92.94,27.69 94.23,27.69 C39.2 C25.2
NETU7/32: length 6.2
  TOP w0.203: U7.32 92.48,31.52 92.84,31.88 92.84,33.15 94.11,34.42 C38.2 C23.2
NETU7/39: length 9.8
  TOP w0.203: C41.1 89.57,42.51 89.63,42.51 89.97,42.18 89.97,39.62 89.41,39.06 89.41,35.66 89.63,35.43 U7.39
NETU7/41: length 7.1
  TOP w0.203: U7.41 88.63,35.17 88.9,35.43 88.9,41.15 C42.1
NETU7/45: length 2.5
  TOP w0.254: R34.2 86.63,36.79 U7.45
NETU8/1: length 9.3
  TOP w0.203: R15.2 55.5,31.88 54.74,32.64 54.74,35.05 55.12,35.43 58.67,35.43 59.32,36.08 U8.1
NETU8/43: length 13.4
  TOP w0.254: U8.43 55,40.78 C75.2 54.86,40.13 54.48,39.75 52.2,39.75 51.31,40.64 49.4,40.64 48.76,41.29 Y2.1
NETU8/44: length 10.9
  TOP w0.254: Y2.2 49,39.5 51.18,39.5 51.42,39.26 53.96,39.26 C76.2 54.86,38.99 56.15,40.28 U8.44
NETU9/1: length 2.7
  TOP w0.508: R61.1 24,111.51 24,110.24 24.26,109.98 U9.1
NETU9/2: length 4.8
  TOP w0.508: U9.2 23.29,109.04 22.16,110.17 21.46,110.17 C46.1
NETU9/3: length 4
  TOP w0.508: C47.1 20.79,108.1 U9.3
NETY5/3: length 4
  TOP w0.254: Y5.3 82.64,51.22 83.69,50.16 83.69,49.43 R27.2
NRESET: length 207.4
  TOP w0.203: LCD1.32 134.26,66.99 130.44,70.82 129.78,70.82 128.84,71.75 128.78,71.75 v1(128.52,72.01) 128.4,72.14 120.24,72.14 116.59,68.48 85.93,68.48 84.91,67.46 72.24,67.46 66.42,73.28 47.24,73.28 v1(46.99,73.53) ; v1(55.37,43.56) 55.5,43.43 55.88,43.43 57.03,42.28 U8.40 ; LCD3.32 175.44,88.43 LCD2.32 168.28,88.43 167.46,89.24 151.72,89.24 150.98,88.49 149.35,88.49 147.49,86.64 131.6,86.64 127.76,82.8 127.76,82.72 v1(127.61,82.57)
  BOTTOM w0.203: v1(46.99,73.53) 46.99,58.99 TINY6410.B42 47.53,56.47 50.63,56.47 52.45,54.66 52.45,46.48 v1(55.37,43.56) ; CON5.17 125,89.76 127.64,87.12 127.64,82.6 v1(127.61,82.57) 128.27,81.92 128.27,72.26 v1(128.52,72.01)
NWAIT: length 14.9
  TOP w0.203: 38.99,52.3 R41.1 41,52.3 43.55,54.85 43.55,56.02 43.09,56.48 43.09,60.38 43.62,60.91 45.09,60.91 TINY6410.B41
OM3: length 204.6
  TOP w0.203: TINY6410.B1 6,63 15.65,72.64 23.64,72.64 24.03,72.26 66.29,72.26 71.96,66.59 86.13,66.59 87.08,67.54 114.89,67.54 119.03,63.4 122.7,63.4 131.5,54.6 152,54.6 153.64,52.96 153.64,39.88 167.92,25.6 167.92,19.89 R2.1
OM4: length 207.1
  TOP w0.203: R21.1 168.45,20.88 168.45,25.86 154.05,40.26 154.05,53.34 152.38,55.01 131.67,55.01 122.87,63.8 119.2,63.8 115.06,67.94 86.61,67.94 85.72,67.06 72.07,67.06 66.35,72.77 24.64,72.77 24.21,73.2 15.54,73.2 5.08,62.74 5.08,58.92 TINY6410.B2
OM34: length 7.9
  TOP w0.203: R21.2 R2.2 173.37,18.41 S2.3
OTGDM: length 138.9
  TOP w0.203: v1(99.31,10.95) 99.31,10.82 99.22,10.73 MINIUSB.2
  BOTTOM w0.203: v1(99.31,10.95) 99.31,11.3 100.36,12.34 103.46,12.34 106.02,14.9 106.02,37.38 105.68,37.72 105.68,37.75 105.06,38.37 105.03,38.37 102.1,41.3 102.1,41.34 94.17,49.27 94.13,49.27 93.34,50.06 86.3,50.06 50.75,85.62 50.75,94.98 46.57,99.16 37.41,99.16 35.08,101.49 35.08,103.08 TINY6410.A31
OTGDP: length 137.9
  TOP w0.203: v1(100.33,11.05) 100.02,10.74 MINIUSB.3
  BOTTOM w0.203: TINY6410.A33 37.08,103.08 37.08,101.22 37.08,100.58 38.1,99.57 46.74,99.57 51.16,95.15 51.16,85.79 86.47,50.47 93.51,50.47 94.42,49.56 94.46,49.56 102.39,41.63 102.39,41.59 105.32,38.66 105.34,38.66 105.97,38.03 105.97,38.01 106.43,37.55 106.43,14.73 103.63,11.94 100.52,11.94 100.17,11.59 100.17,11.21 v1(100.33,11.05)
OTGID: length 139.8
  TOP w0.203: v1(47.12,86.36) 46.78,86.36 46.63,86.21 44.94,86.21 44.07,87.08 44.07,88.07 33.05,99.09 33.05,103.05 TINY6410.A29 ; MINIUSB.4 v1(100.83,7.25)
  BOTTOM w0.203: v1(47.12,86.36) 47.12,85.95 85.19,47.88 93.98,47.88 99.89,41.97 99.89,41.62 100.86,40.64 100.86,24.99 104.04,21.82 104.04,18.41 102.87,17.25 102.87,16.51 103.82,15.56 103.82,14.79 102.49,13.46 100.89,13.46 98.65,11.22 98.65,9.42 v1(100.83,7.25)
PWM0: length 170
  TOP w0.203: v1(77.98,100.2) 77.34,100.2 75.31,102.23 66.17,102.23 64.77,100.84 57.16,100.84 TINY6410.A52 ; R23.1 150.52,21.59 v1(158.88,21.59)
  BOTTOM w0.203: v1(77.98,100.2) 78.36,99.82 78.36,99.57 80.49,97.43 80.81,97.43 82.22,96.02 82.22,87.76 82.7,87.28 82.7,86.75 89.15,80.29 89.15,65.47 90.5,64.12 90.5,63.95 91.15,63.3 91.39,63.3 92.33,62.36 92.33,61.21 99.8,53.75 102,53.75 102.39,53.36 102.39,52.81 102.01,52.43 102.01,51.54 113.06,40.49 118.92,40.49 121.16,38.25 153.26,38.25 158.42,33.1 158.42,22.05 v1(158.88,21.59)
PWM1: length 190.6
  TOP w0.203: LCD3.31 177.05,88.04 175.9,88.04 175.78,87.93 LCD2.31 168.2,87.93 167.29,88.83 151.95,88.83 151,87.88 149.31,87.88 147.66,86.23 132.21,86.23 v1(129.03,83.06) 127.74,81.76 127.28,81.76 126.78,81.25 115.81,81.25 112.07,77.52 76.4,77.52 71.26,82.67 40.78,82.67 26,97.44 TINY6410.A22 ; LCD1.31 134.76,67.07 130.61,71.22 130.36,71.22 v1(129.94,71.64)
  BOTTOM w0.203: v1(129.94,71.64) 129.92,71.66 129.92,72.01 129.03,72.9 v1(129.03,83.06)
RSCTS1: length 63.8
  TOP w0.203: v1(86.49,98.91) 86.49,98.81 85.22,97.54 U2.8
  BOTTOM w0.203: COM1.8 46.44,120.14 46.29,120.14 45.34,119.19 45.34,117.35 46.99,115.7 79.38,115.7 85.01,110.06 85.01,104.24 85.14,104.12 85.14,99.9 86.13,98.91 v1(86.49,98.91)
RSRTS1: length 58.9
  TOP w0.203: v1(85.8,100.2) 85.72,100.13 85.72,99.69 84.84,98.81 U2.7
  BOTTOM w0.203: v1(85.8,100.2) 85.55,100.46 85.55,104.29 85.42,104.41 85.42,110.41 79.73,116.1 49.49,116.1 48.37,117.22 48.37,119.48 49.03,120.14 49.18,120.14 COM1.7
RSRXD0: length 174.8
  TOP w0.203: U1.13 103.5,102.62 v1(103.89,102.23) ; v1(45.85,96.9) 45.85,96.62 46.53,95.94 48.46,95.94 51.66,92.74 52.81,92.74 54.74,90.81 65.52,90.81 67.42,88.9 102.66,88.9 v1(103.53,89.77)
  BOTTOM w0.203: v1(103.89,102.23) 103.89,91.44 103.61,91.16 103.61,89.84 v1(103.53,89.77) ; COM0.2 35.26,22.15 29.97,27.43 29.97,51.82 31.24,53.09 35.81,53.09 39.09,56.36 39.09,57.62 39.09,57.62 39.09,60.38 39.09,60.38 39.09,91.21 39.48,91.59 39.9,91.59 45.21,96.9 v1(45.85,96.9)
RSRXD1: length 48.8
  TOP w0.203: U2.13 87.76,102.62 v1(87.63,102.74)
  BOTTOM w0.203: COM1.2 54.03,117.22 80.34,117.22 88.54,109.01 88.54,103.61 87.78,102.85 87.74,102.85 v1(87.63,102.74)
RSRXD2: length 27.4
  TOP w0.203: v1(93.98,97.54) U1.8
  BOTTOM w0.203: v1(93.98,97.54) 95.58,99.14 95.58,103.43 87.24,111.77 87.24,118.98 COM2.2
RSTXD0: length 175.1
  TOP w0.203: U1.14 103.53,103.89 v1(104.01,103.4) ; v1(47.5,96.62) 47.75,96.37 48.79,96.37 51.94,93.22 53.09,93.22 54.86,91.44 65.77,91.44 67.89,89.33 102.15,89.33 103.63,90.81 104.24,90.81 v1(104.27,90.83)
  BOTTOM w0.203: COM0.3 38,20.04 30.48,27.56 30.48,51.44 31.62,52.58 36.07,52.58 41.02,57.53 41.02,90.14 45.19,94.31 45.19,95.14 45.57,95.53 46.41,95.53 v1(47.5,96.62) ; v1(104.01,103.4) 104.55,102.87 104.55,91.11 v1(104.27,90.83)
RSTXD1: length 48.9
  TOP w0.203: U2.14 v1(87.88,103.89)
  BOTTOM w0.203: COM1.3 52,116.51 80.21,116.51 87.88,108.84 v1(87.88,103.89)
RSTXD2: length 27.3
  TOP w0.203: v1(93.98,98.81) U1.7
  BOTTOM w0.203: v1(93.98,98.81) 94.11,98.93 94.74,98.93 95.15,99.34 95.15,103.29 86.64,111.79 86.64,116.81 84.5,118.96 84.5,118.98 COM2.3
RTSN1: length 199.3
  TOP w0.203: v1(80.22,95.76) 80.52,95.76 81.18,96.42 86,96.42 88.39,98.81 U2.10 ; CON5.10 116.99,93.5 116.06,92.56 116.06,91.11 115.42,90.47 114.6,90.47 113.67,89.53 113.42,89.53 111.33,87.45 107.62,87.45 107.32,87.15 82.97,87.15 82.44,87.67 81.67,87.67 81.35,87.35 v1(80.56,87.35) ; TINY6410.B5 9.58,60.42 9.58,62.15 15.98,68.55 23.3,68.55 25.08,70.33 67.07,70.33 71.62,65.78 87.11,65.78 v1(87.38,66.04)
  BOTTOM w0.203: v1(87.38,66.04) 87.17,66.24 87.17,79.38 84.94,81.61 84.94,82.5 80.56,86.88 v1(80.56,87.35) 80.38,87.52 80.38,94.84 80.22,94.99 v1(80.22,95.76) 80.01,95.76 70.36,105.41 70.36,106.3 67.18,109.47 59.82,109.47 58.07,111.22 CON2.1
RXD0: length 165.2
  TOP w0.203: v1(84.75,95.29) 84.9,95.15 96.42,95.15 98.93,97.66 98.93,100.58 99.69,101.35 U1.12 ; TINY6410.B8 11.09,58.91 11.09,62.59 16.65,68.15 23.47,68.15 25.25,69.93 66.9,69.93 71.93,64.9 87.25,64.9 88.57,66.22 91.31,66.22 v1(91.37,66.28)
  BOTTOM w0.203: CON1.2 74.93,111.76 82.58,104.11 82.58,99.54 84.75,97.36 v1(84.75,95.29) 84.75,95.21 84.65,95.1 84.65,89.62 90.88,83.38 90.88,66.77 v1(91.37,66.28)
RXD1: length 197.1
  TOP w0.203: v1(84.07,88.24) 84.35,87.96 106.98,87.96 107.29,88.27 111,88.27 113.29,90.56 113.39,90.56 113.94,91.11 113.94,91.77 115,92.83 CON5.8 ; U2.12 88.77,101.35 87,99.57 86.17,99.57 84.78,98.17 82.17,98.17 v1(81.94,98.4) ; TINY6410.B10 13.09,58.91 13.09,62.74 17.68,67.34 23.81,67.34 25.59,69.11 66.56,69.11 71.8,63.88 89.68,63.88 89.73,63.93 90.6,63.93 91.06,64.39 v1(91.57,64.39)
  BOTTOM w0.203: v1(91.57,64.39) 91.49,64.39 90.07,65.81 90.07,82.27 84.1,88.24 v1(84.07,88.24) 83.21,89.1 83.21,97.13 v1(81.94,98.4) 81.69,98.65 81.69,103.85 75.43,110.11 68.79,110.11 68.1,110.79 64.59,110.79 64.07,111.32 CON2.4
RXD2: length 227.2
  TOP w0.203: v1(79.73,86.87) 80.26,86.33 109.11,86.33 109.41,86.64 111.67,86.64 113.58,88.54 114.1,88.54 115.04,89.48 115.77,89.48 116.76,90.47 117.53,90.47 117.98,90.93 117.98,92.46 119,93.47 CON5.12 ; v1(79.71,94.37) 79.71,94.31 80.22,93.8 96.97,93.8 100.71,97.54 U1.9 ; v1(90.17,62.87) 90.07,62.76 71.76,62.76 66.23,68.3 25.92,68.3 24.14,66.52 19.79,66.52 14.99,61.72 14.99,59.01 TINY6410.B12
  BOTTOM w0.203: v1(90.17,62.87) 89.6,62.87 86.56,65.9 86.56,79.15 84.35,81.36 84.35,82.27 79.76,86.87 v1(79.73,86.87) 79.76,86.89 79.76,94.32 v1(79.71,94.37) 79.71,94.81 79.63,94.88 79.63,95.32 71.15,103.79 69.93,105.02 69.93,106.05 67,108.97 59.08,108.97 57.36,110.68 50.26,110.68 49.02,111.92 CON3.2
RXD3: length 166.9
  TOP w0.203: v1(89.8,61.38) 78.87,61.38 78.46,61.8 71.58,61.8 65.89,67.49 26.26,67.49 24.48,65.71 20.75,65.71 17.27,62.23 17.27,60.57 17.09,60.38 17.09,58.91 TINY6410.B14
  BOTTOM w0.203: v1(89.8,61.38) 89.8,61.51 83.67,67.65 83.67,71.19 66.62,88.24 66.62,104.7 64.97,106.35 44.02,106.35 37.97,112.39 CON4.2
SD0_CLK: length 28.4
  TOP w0.203: CON6.5 30.9,43.02 30.92,43 32.18,43 R7.1 32.97,43.79 32.97,44.7 34.96,46.7 34.96,48.74 35.37,49.15 35.37,50.78 34.16,51.98 34.16,54.41 32.69,55.88 v1(32.36,55.88)
  BOTTOM w0.203: v1(32.36,55.88) 32.28,55.96 31.75,55.96 31.06,56.64 25.91,56.64 25.09,57.46 25.09,59.09 TINY6410.B21
SD0_CMD: length 33
  TOP w0.203: CON6.2 31.65,35.61 R9.1 34.26,38.23 34.92,38.23 35.37,38.67 35.37,48.57 35.78,48.98 35.78,50.95 34.67,52.05 34.67,54.66 32.51,56.82 v1(32.13,56.82)
  BOTTOM w0.203: TINY6410.B22 26.93,57.07 31.88,57.07 v1(32.13,56.82)
SD0_DAT0: length 19.2
  TOP w0.203: TINY6410.B25 31.08,58.92 31.08,55.28 33.66,52.7 33.66,51.92 34.96,50.61 34.96,49.31 34.8,49.15 33.45,49.15 32.61,48.31 R6.1 32.13,47.78 32.13,47.02 31.21,47.94 CON6.7
SD0_DAT1: length 11.5
  TOP w0.203: CON6.8 32.22,49.65 R4.1 32.13,50.52 32.13,53.34 30.58,54.89 30.58,57.42 TINY6410.B26
SD0_DAT2: length 37.6
  TOP w0.203: TINY6410.B27 33.02,58.98 33.02,57.66 35.69,54.99 35.69,52.18 36.59,51.28 36.59,48.62 38.82,46.39 38.82,37.87 36.23,35.27 36.23,33.38 34.95,32.11 33.86,32.11 R12.1 32.28,30.53 CON6.9
SD0_DAT3: length 33.2
  TOP w0.203: CON6.1 32.41,33.07 R10.1 33.15,33.81 33.15,34.47 33.91,35.23 35.61,35.23 38.42,38.04 38.42,46.22 36.18,48.45 36.18,51.11 35.18,52.12 35.18,54.82 32,58 TINY6410.B28
SD0_NCD: length 30.3
  TOP w0.203: TINY6410.B23 26.91,58.91 26.91,56.26 26.7,56.04 26.7,37.57 27.04,37.22 CON6.11 31.02,37.22 32.26,38.46 32.26,39.01 R3.1
SD0_NWP: length 7.1
  TOP w0.203: TINY6410.B24 28,58 28,53.41 28.4,53.01 CON6.10
SD1_CLK: length 119.9
  TOP w0.203: TINY6410.A43 47.09,103.09 47.09,100.74 48.28,99.55 48.79,99.55 55.5,92.84 70.26,92.84 R19.1 71.5,93.6 74.56,90.54 101.65,90.54 112.14,101.04 146.79,101.04 149.94,97.89 149.94,96.61 151.03,95.52 151.03,95.5 CON11.13
SD1_CMD: length 116.2
  TOP w0.203: CON11.14 151,99.87 149.43,101.45 111.98,101.45 101.48,90.95 75.01,90.95 71.02,94.94 R74.1 70.27,94.37 68.14,94.37 67.65,94.87 54.15,94.87 49.02,100 49.02,100.98 TINY6410.A44
SD1_DAT0: length 124.1
  TOP w0.203: CON11.17 153.99,96.51 153.99,100.62 151.94,102.67 112.14,102.67 112.14,102.67 111.47,102.67 100.97,92.17 75.72,92.17 72.61,95.29 72.61,96.03 72.24,96.4 72.24,98.48 R71.1 70.87,99.69 70.09,98.92 67.17,98.92 65.94,97.69 54.16,97.69 51.31,100.54 51.31,101.4 51.09,101.62 51.09,103.09 TINY6410.A47
SD1_DAT1: length 120.2
  TOP w0.203: TINY6410.A48 52.96,101.04 52.96,100.33 55.19,98.09 65.71,98.09 68.07,100.45 71.61,100.45 72.64,99.42 72.64,97.54 73.13,97.05 73.13,95.43 74.32,94.23 75.72,94.23 R76.1 76.64,95 79.06,92.58 100.81,92.58 111.3,103.07 152.22,103.07 154.53,100.76 154.53,97.97 CON11.18
SD1_DAT2: length 124.1
  TOP w0.203: TINY6410.A49 53.72,103.72 53.68,103.72 53.09,103.12 53.09,101.62 53.47,101.24 53.47,100.44 55.4,98.5 65.23,98.5 67.64,100.91 71.72,100.91 73.05,99.58 73.05,97.76 73.55,97.27 75.5,97.27 76.25,96.52 R72.1 76.58,96.52 77.25,95.85 77.25,95.08 79.36,92.98 100.64,92.98 111.16,103.5 152.73,103.5 155.99,100.24 155.99,96.51 CON11.19
SD1_DAT3: length 118.1
  TOP w0.203: TINY6410.A50 54.99,101.01 54.99,100.97 57.05,98.91 64.62,98.91 67.03,101.32 73.2,101.32 R77.1 77.66,96.86 77.66,95.36 79.63,93.39 100.47,93.39 111.09,104.01 153.03,104.01 157,100.05 CON11.20
SD1_NCD: length 122.1
  TOP w0.203: CON11.15 151.99,96.51 151.99,99.62 149.76,101.85 111.81,101.85 101.31,91.36 75.18,91.36 71.79,94.74 71.79,95.69 71.02,96.47 R20.1 70.99,96.65 70.24,95.9 67.94,95.9 67.42,95.38 54.23,95.38 49.58,100.03 49.58,101.13 49.09,101.62 49.09,103.09 TINY6410.A45
SD1_NWP: length 117
  TOP w0.203: CON11.16 153,99.32 150.06,102.26 111.64,102.26 101.14,91.76 75.35,91.76 72.2,94.91 72.2,95.86 71.83,96.23 71.83,97.36 R75.1 70.99,98.17 70.22,97.4 66.66,97.4 66.55,97.28 53.98,97.28 50.9,100.36 50.9,101.1 TINY6410.A46
SDBOOT: length 6.4
  TOP w0.203: R22.1 171.58,15.37 174.37,12.57 S2.4
SPICLK: length 214
  TOP w0.203: CON5.16 123,94.26 124.01,95.28 131.62,95.28 134.23,92.66 145.11,92.66 147,94.55 CON11.9 ; v1(150.34,51.44) 132.21,51.44 123.07,60.58 93.85,60.58 91.97,58.7 74.14,58.7 73.08,59.77 70.74,59.77 65.05,65.46 27.99,65.46 25.86,63.32 24.84,63.32 22,60.48 TINY6410.B17
  BOTTOM w0.203: CON11.9 147,95.32 153.03,89.29 153.03,67.12 150.34,64.42 150.34,52.85 150.22,52.72 150.22,52.18 150.34,52.05 v1(150.34,51.44)
SPICS: length 224.7
  TOP w0.203: TINY6410.B18 21.09,58.91 21.09,60.96 21.63,61.5 21.63,62.57 23.13,64.08 25.73,64.08 27.51,65.86 65.22,65.86 70.91,60.17 73.58,60.17 74.65,59.11 91.44,59.11 93.42,61.09 123.14,61.09 132.03,52.2 150.62,52.2 v1(150.88,52.45) ; CON11.10 147,96.97 147.94,96.03 147.94,94.6 145.59,92.25 134.07,92.25 131.45,94.87 124.51,94.87 123.95,94.31 123.95,92.9 123.65,92.61 123.65,92.15 CON5.15
  BOTTOM w0.203: CON11.10 147.94,96.56 147.94,94.96 153.44,89.46 153.44,66.95 151,64.51 151,52.58 v1(150.88,52.45)
SPIMISO: length 221.4
  TOP w0.203: TINY6410.B16 19.09,58.91 19.09,60.38 19.3,60.6 19.3,62.74 21.46,64.9 24.82,64.9 26.6,66.67 65.55,66.67 71.24,60.99 73.92,60.99 74.98,59.92 90.73,59.92 93.04,62.23 123.14,62.23 131.43,53.94 v1(149.61,53.94) ; CON5.14 121,93.82 123.29,96.11 131.93,96.11 134.57,93.47 142.43,93.47 143.94,94.99 143.94,95.81 145,96.87 CON11.8
  BOTTOM w0.203: CON11.8 146.06,96.44 146.06,95.11 146.83,94.34 147.22,94.34 152.63,88.93 152.63,67.28 149.61,64.26 v1(149.61,53.94)
SPIMOSI: length 216.4
  TOP w0.203: v1(148.72,53.09) 148.5,53.3 131.49,53.3 123.2,61.59 93.27,61.59 91.19,59.51 74.81,59.51 73.75,60.58 71.07,60.58 65.38,66.27 26.77,66.27 24.99,64.49 21.94,64.49 20,62.54 TINY6410.B15 ; CON5.13 122.05,92.55 122.05,94.23 123.52,95.71 131.76,95.71 134.4,93.07 143.36,93.07 145,94.71 CON11.7
  BOTTOM w0.203: v1(148.72,53.09) 148.95,53.31 148.95,64.18 152.22,67.45 152.22,88.68 147.07,93.83 146.67,93.83 CON11.7
SUB_DM1: length 117.3
  TOP w0.203: U6.27 116.66,54.12 116.76,54.22 117.21,54.22 118.42,55.43 118.81,55.43 119.35,54.89 R44.1 119.38,54.74 120.14,55.5 122.19,55.5 v1(122.3,55.39)
  BOTTOM w0.203: USBH1.2 166.25,115.87 164.77,115.87 160.27,111.38 160.27,104.39 162.69,101.98 162.69,61.09 151.89,50.29 148.21,50.29 146.18,48.26 132.72,48.26 125.43,55.55 122.5,55.55 122.48,55.57 v1(122.3,55.39)
SUB_DM2: length 78.4
  TOP w0.203: R50.1 104.8,53.98 105.28,53.98 105.92,54.61 106.22,54.61 v1(106.5,54.89) 106.62,54.77 U6.1
  BOTTOM w0.203: USBH2.2 166.35,46.76 163.47,46.76 157.25,40.54 128.55,40.54 128.02,40.01 122.38,40.01 120.35,42.04 114.81,42.04 105.27,51.57 105.27,54.1 106.06,54.89 v1(106.5,54.89)
SUB_DM3: length 130.7
  TOP w0.203: U6.3 107.19,53.47 105.03,51.31 R52.1 104.39,51.31 103.62,52.08 101.89,52.08 101.62,52.35 100.59,52.35 v1(100.46,52.48)
  BOTTOM w0.203: v1(100.46,52.48) 100.17,52.2 99.45,52.2 91.44,60.21 88.04,60.21 81.31,66.94 81.31,71.21 65.78,86.74 65.78,104.28 64.52,105.54 27.56,105.54 23.27,109.83 23.27,116.23 USBH3.2
SUB_DP1: length 117.6
  TOP w0.203: v1(122.3,56.39) 122.04,56.13 120.14,56.13 119.38,56.9 R49.1 119.35,56.62 118.62,55.89 118.23,55.89 117.02,54.68 116.76,54.68 116.66,54.77 U6.28
  BOTTOM w0.203: USBH1.3 166.45,116.33 164.58,116.33 159.82,111.57 159.82,104.2 162.23,101.79 162.23,61.28 151.7,50.75 148.02,50.75 145.99,48.72 132.9,48.72 125.61,56.01 122.69,56.01 v1(122.3,56.39)
SUB_DP2: length 76.9
  TOP w0.203: U6.2 106.88,54.12 v1(106.6,53.85) 105.8,53.85 105.47,53.52 105.11,53.52 R51.1
  BOTTOM w0.203: v1(106.6,53.85) 106.35,54.1 105.92,54.1 105.73,53.91 105.73,51.76 115,42.49 120.53,42.49 122.57,40.46 127.83,40.46 128.36,41 157.06,41 163.28,47.21 166.35,47.21 USBH2.3
SUB_DP3: length 132.1
  TOP w0.203: U6.4 107.3,52.82 104.42,49.94 R53.1 103.64,50.56 101.54,50.56 100.64,51.46 v1(100.46,51.46)
  BOTTOM w0.203: USBH3.3 22.81,116.23 22.81,109.64 27.37,105.08 64.33,105.08 65.32,104.09 65.32,86.55 80.85,71.02 80.85,66.75 87.85,59.75 91.25,59.75 99.31,51.69 100.23,51.69 v1(100.46,51.46)
TSXM: length 185.6
  TOP w0.203: v1(117.35,84.33) 117.42,84.4 122.88,84.4 123.11,84.63 125.27,84.63 125.58,84.93 126.16,84.93 130.25,89.03 146.5,89.03 149.81,92.33 159.16,92.33 159.78,92.95 166.18,92.95 167.01,92.13 167.45,92.13 168.65,90.93 LCD2.37 173.35,90.93 174.09,91.67 174.09,92.98 175.03,93.92 176.93,93.92 LCD3.37 ; v1(115.44,84.96) 115.34,84.96 114.57,84.2 114.57,84.03 113.78,83.24 111.9,83.24 111.59,83.54 77.41,83.54 76.74,83.54 73.93,86.35 65.34,86.35 65.09,86.6 65.04,86.6 63.56,88.09 53.1,88.09 53.02,88.16 52.42,88.16 47.87,92.71 44.83,92.71 39.47,98.07 39.47,101.47 TINY6410.A36 ; v1(123.19,71.25) 123.22,71.22 123.34,71.22 C69.1 126.7,67.87 130.51,67.87 131.76,66.62 LCD1.37
  BOTTOM w0.203: v1(123.19,71.25) 122.68,71.25 115.7,78.23 115.7,83.06 116.97,84.33 ; 116.97,84.33 v1(117.35,84.33) ; 116.97,84.33 116.33,84.96 v1(115.44,84.96)
TSXP: length 188
  TOP w0.203: LCD1.38 131.26,66.54 130.34,67.46 125.58,67.46 C72.1 123.98,69.06 123.8,69.06 123.39,69.47 v1(121.79,69.47) ; TINY6410.A35 39.02,103.02 39.02,97.43 44.37,92.08 47.66,92.08 51.98,87.76 52.85,87.76 52.93,87.68 63.39,87.68 64.87,86.19 64.92,86.19 65.17,85.94 73.76,85.94 76.57,83.13 77.58,83.13 111.42,83.13 111.73,82.83 113.94,82.83 115.19,84.07 v1(115.7,84.07) 116.69,85.06 122.94,85.06 122.97,85.04 125.11,85.04 125.61,85.54 126.19,85.54 130.08,89.43 146.34,89.43 149.64,92.74 158.72,92.74 159.35,93.36 166.35,93.36 167.18,92.53 167.62,92.53 168.72,91.43 LCD2.38 173.21,91.43 173.69,91.9 173.69,93.92 174.75,94.98 LCD3.38
  BOTTOM w0.203: v1(115.7,84.07) 114.94,83.31 114.94,78.16 119.63,73.46 119.63,70.82 120.99,69.47 v1(121.79,69.47)
TSYM: length 185.8
  TOP w0.203: TINY6410.A38 41.7,101.7 41.7,97.62 43.94,95.38 44.2,95.38 45.59,93.98 47.75,93.98 52.75,88.98 53.36,88.98 53.43,88.9 63.89,88.9 65.38,87.41 65.42,87.41 65.68,87.16 74.27,87.16 77.07,84.35 112.5,84.35 112.52,84.33 v1(112.6,84.33) ; LCD1.39 130.76,66.47 130.18,67.06 124.46,67.06 C70.1 124.33,67.31 123.7,67.94 121.79,67.94 v1(121.54,67.69) ; LCD3.39 176.93,95.92 175.11,95.92 173.28,94.09 173.28,92.13 173.08,91.93 LCD2.39 168.99,91.93 167.98,92.94 167.34,92.94 166.52,93.76 158.84,93.76 158.22,93.14 149.47,93.14 146.17,89.84 129.91,89.84 127.27,87.2 126.7,87.2 125.45,85.95 125.44,85.95 125.09,85.6 115.74,85.6 115.72,85.62 115.17,85.62 115.14,85.6 114.94,85.6 114.3,84.96 v1(114.3,84.86)
  BOTTOM w0.203: v1(112.6,84.33) 112.77,84.33 113.31,84.86 v1(114.3,84.86) 114.3,77.72 119.23,72.8 119.23,69.7 120.88,68.05 121.18,68.05 v1(121.54,67.69)
TSYP: length 189.6
  TOP w0.203: LCD1.40 130.26,66.21 130.05,66.42 125.09,66.42 C71.1 123.7,65.02 v1(123.7,64.14) ; TINY6410.A37 41.09,103.09 41.09,97.47 45.21,93.34 47.81,93.34 52.59,88.57 53.19,88.57 53.26,88.49 63.72,88.49 65.21,87.01 65.25,87.01 65.51,86.75 74.1,86.75 76.91,83.95 111.76,83.95 112.07,83.64 113.08,83.64 113.33,83.9 v1(113.41,83.9) 113.41,84.96 114.48,86.03 124.95,86.03 125.27,86.35 125.28,86.35 125.82,86.89 126.53,87.6 127.1,87.6 129.67,90.17 129.74,90.25 146,90.25 149.48,93.73 157.13,93.73 157.74,94.34 166.52,94.34 167.51,93.35 168.15,93.35 169.07,92.43 LCD2.40 172.69,92.43 172.85,92.58 172.85,94.36 175.46,96.98 LCD3.40
  BOTTOM w0.203: v1(123.7,64.14) 123.4,64.14 118.24,69.3 118.24,72.9 113.79,77.34 113.79,83.52 v1(113.41,83.9)
TXD0: length 165.7
  TOP w0.203: v1(83.95,94.86) 84.2,94.61 96.45,94.61 99.44,97.6 99.44,98.93 100.58,100.08 U1.11 ; v1(92.27,65.34) 92.2,65.28 91.06,65.28 90.17,64.39 71.86,64.39 66.73,69.52 25.42,69.52 23.64,67.74 16.81,67.74 11.68,62.61 11.68,60.32 TINY6410.B7
  BOTTOM w0.203: v1(92.27,65.34) 91.37,65.34 90.47,66.24 90.47,82.79 83.95,89.32 v1(83.95,94.86) 83.95,97.41 82.17,99.19 82.17,103.95 75.12,111 74.04,111 72.93,112.11 CON1.1
TXD1: length 197.6
  TOP w0.203: v1(83.11,87.94) 83.49,87.55 107.15,87.55 107.45,87.86 111.17,87.86 113.25,89.94 113.46,89.94 115,91.48 CON5.7 ; TINY6410.B9 14,62.72 18.21,66.93 23.98,66.93 25.76,68.71 66.39,68.71 71.73,63.37 89.74,63.37 89.9,63.53 91.97,63.53 v1(92.33,63.88) ; v1(82.17,97.08) 82.35,96.9 85.72,96.9 88.9,100.08 U2.11
  BOTTOM w0.203: CON2.3 62.07,111.03 62.71,110.39 67.93,110.39 68.72,109.6 75.36,109.6 77.62,107.34 81.28,103.69 81.28,97.97 v1(82.17,97.08) 82.17,97.03 82.8,96.39 82.8,88.24 v1(83.11,87.94) 83.11,87.83 83.41,87.53 84.07,87.53 89.66,81.94 89.66,65.53 90.91,64.29 90.91,64.12 91.32,63.7 92.15,63.7 v1(92.33,63.88)
